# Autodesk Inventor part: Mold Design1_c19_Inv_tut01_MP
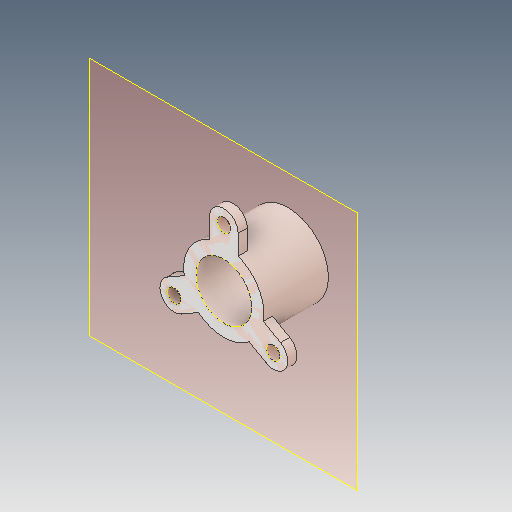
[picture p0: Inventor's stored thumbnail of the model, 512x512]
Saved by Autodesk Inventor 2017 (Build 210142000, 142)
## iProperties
Created: 2016-07
Part Number: Mold Design1_c19_Inv_tut01_MP
Material: Generic
Document SubType Name: Modeling
Designer: Sandeep
Density: 1 g/cm^3
Appearance: Default
Author: Sandeep
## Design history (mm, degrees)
derived "c19_Inv_tut01.ipt"
node "Mold Design1_c19_Inv_tut01_WP"
patch "Boundary Patch1" dims "d7" = 5, "d8" = 0
patch "Boundary Patch2" dims "d9" = 5, "d10" = 0
patch "Boundary Patch3" dims "d11" = 5, "d12" = 0
patch "Boundary Patch4" dims "d13" = 5, "d14" = 0
workplane "Work Plane1"
sketch "Sketch1"
  geometry: L1 (371.75, -369.93)-(371.75, 470.07); L2 (371.75, 470.07)-(-565.75, 470.07); L3 (-565.75, 470.07)-(-565.75, -369.93); L4 (-565.75, -369.93)-(371.75, -369.93); C1 r 97 at (-97, 0) reference; 1 further point
  constraints: 8 end point
  dimensions: "d15" = 468.75 horizontal distance of point (-97, 50.07) L1.end (= 1.5 x Xmax); "d16" = 420 vertical distance of point (-97, 50.07) L1.end (= 1.5 x Ymax); "d17" = 468.75 horizontal distance of point (-97, 50.07) L2.end (= -1.5 x Xmin); "d18" = 420 vertical distance of point (-97, 50.07) L2.end (= 1.5 x Ymax); "d19" = 468.75 horizontal distance of point (-97, 50.07) L3.end (= -1.5 x Xmin); "d20" = 420 vertical distance of point (-97, 50.07) L3.end (= -1.5 x Ymin); "d21" = 468.75 horizontal distance of point (-97, 50.07) L1.start (= 1.5 x Xmax); "d22" = 420 vertical distance of point (-97, 50.07) L1.start (= -1.5 x Ymin)
patch "Boundary Patch5" sketch "Sketch1"
feature "Cavity Separation1"
feature "Solid1::c19_Inv_tut01.ipt"
tag "TaggingFeature1"
feature "Solid1::Mold Design1_c19_Inv_tut01_WP"
tag "TaggingFeature2"
body "Srf1"
body "Srf2"
body "Srf3"
body "Srf4"
body "Srf5"
body "Solid3"
body "Solid4"
body "Solid1"
feature "c19_Inv_tut01.ipt_Bodies"
body "Solid2"
feature "Mold Design1_c19_Inv_tut01_WP_Bodies"
other parameters: "d0" = -157.5, "d1" = 312.5, "d2" = 312.5, "d5" = 315, "d6" = 0, "Xmin" = -312.5, "Zmin" = -157.5, "Xmax" = 312.5, "Zmax" = 157.5
